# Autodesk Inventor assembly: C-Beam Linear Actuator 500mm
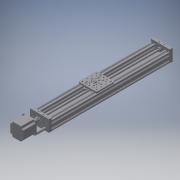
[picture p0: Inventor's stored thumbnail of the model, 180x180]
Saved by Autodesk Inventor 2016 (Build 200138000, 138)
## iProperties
Created: 2015-08
Part Number: C-Beam Linear Actuator 500mm
Description: STEP AP203
Document SubType Name: Assembly
Designer: John
Title: C-Beam Linear Actuator 500mm.step
Revision Number: ANY
Sending System: SolidWorks 2014
Preprocessor: SwSTEP 2.0
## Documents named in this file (19)
- D:\3D Printer Designs\John Ledden Designs\DLP Printer\STEP Parts Library 1.1\Assemblies\C-Beam Linear Actuator\C-Beam Linear Actuator 500mm.iam
- D:\3D Printer Designs\John Ledden Designs\DLP Printer\STEP Parts Library 1.1\Assemblies\C-Beam Linear Actuator\Low Profile Screw M5_M5 x 20.ipt
- D:\3D Printer Designs\John Ledden Designs\DLP Printer\STEP Parts Library 1.1\Assemblies\C-Beam Linear Actuator\Nylon Insert Lock Nut M5.ipt
- D:\3D Printer Designs\John Ledden Designs\DLP Printer\STEP Parts Library 1.1\Assemblies\C-Beam Linear Actuator\Low Profile Screw M5_M5 x 25.ipt
- D:\3D Printer Designs\John Ledden Designs\DLP Printer\STEP Parts Library 1.1\Assemblies\C-Beam Linear Actuator\Low Profile Screw M5_M5 x 55.ipt
- D:\3D Printer Designs\John Ledden Designs\DLP Printer\STEP Parts Library 1.1\Assemblies\C-Beam Linear Actuator\C-Beam End Mount.ipt
- D:\3D Printer Designs\John Ledden Designs\DLP Printer\STEP Parts Library 1.1\Assemblies\C-Beam Linear Actuator\C-Beam 40x80x500 Linear Rail.ipt
- D:\3D Printer Designs\John Ledden Designs\DLP Printer\STEP Parts Library 1.1\Assemblies\C-Beam Linear Actuator\Ball Bearing 8 x 16 x 5.ipt
- D:\3D Printer Designs\John Ledden Designs\DLP Printer\STEP Parts Library 1.1\Assemblies\C-Beam Linear Actuator\Shim Washer 8mm.ipt
- D:\3D Printer Designs\John Ledden Designs\DLP Printer\STEP Parts Library 1.1\Assemblies\C-Beam Linear Actuator\Lock Collar 8mm.ipt
- D:\3D Printer Designs\John Ledden Designs\DLP Printer\STEP Parts Library 1.1\Assemblies\C-Beam Linear Actuator\Aluminum Spacer 40mm.ipt
- D:\3D Printer Designs\John Ledden Designs\DLP Printer\STEP Parts Library 1.1\Assemblies\C-Beam Linear Actuator\Nema 23 Stepper Motor.ipt
- D:\3D Printer Designs\John Ledden Designs\DLP Printer\STEP Parts Library 1.1\Assemblies\C-Beam Linear Actuator\Flexible Coupling 0.25in x 8mm.ipt
- D:\3D Printer Designs\John Ledden Designs\DLP Printer\STEP Parts Library 1.1\Assemblies\C-Beam Linear Actuator\8mm leadscrew 540mm.ipt
- D:\3D Printer Designs\John Ledden Designs\DLP Printer\STEP Parts Library 1.1\Assemblies\C-Beam Linear Actuator\C-Beam Gantry Plate.ipt
- D:\3D Printer Designs\John Ledden Designs\DLP Printer\STEP Parts Library 1.1\Assemblies\C-Beam Linear Actuator\8mm Acme Nut Block.ipt
- D:\3D Printer Designs\John Ledden Designs\DLP Printer\STEP Parts Library 1.1\Assemblies\C-Beam Linear Actuator\Xtreme Mini V Wheel_Straight.iam
- D:\3D Printer Designs\John Ledden Designs\DLP Printer\STEP Parts Library 1.1\Assemblies\C-Beam Linear Actuator\Xtreme Mini V Wheel_Eccentric.iam
- D:\3D Printer Designs\John Ledden Designs\DLP Printer\STEP Parts Library 1.1\Assemblies\C-Beam Linear Actuator\Aluminum Spacer 3mm.ipt
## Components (40 placed, 40 different names)
1. Low Profile Screw M5_M5 x 20_1
2. Low Profile Screw M5_M5 x 20_2
3. Low Profile Screw M5_M5 x 20_3
4. Low Profile Screw M5_M5 x 20_4
5. Low Profile Screw M5_M5 x 20_5
6. Low Profile Screw M5_M5 x 20_6
7. Low Profile Screw M5_M5 x 20_7
8. Low Profile Screw M5_M5 x 20_8
9. Nylon Insert Lock Nut M5_9
10. Nylon Insert Lock Nut M5_10
11. Low Profile Screw M5_M5 x 20_11
12. Low Profile Screw M5_M5 x 20_12
13. Low Profile Screw M5_M5 x 25_13
14. Low Profile Screw M5_M5 x 25_14
15. Low Profile Screw M5_M5 x 25_15
16. Low Profile Screw M5_M5 x 25_16
17. Low Profile Screw M5_M5 x 55_17
18. Low Profile Screw M5_M5 x 55_18
19. C-Beam End Mount_19
20. C-Beam 40x80x500 Linear Rail_20
21. C-Beam End Mount_21
22. Ball Bearing 8 x 16 x 5_22
23. Ball Bearing 8 x 16 x 5_23
24. Shim Washer 8mm_24
25. Shim Washer 8mm_25
26. Lock Collar 8mm_26
27. Lock Collar 8mm_27
28. Aluminum Spacer 40mm_28
29. Aluminum Spacer 40mm_29
30. Nema 23 Stepper Motor_30
31. Flexible Coupling 0.25in x 8mm_31
32. 8mm leadscrew 540mm_32
33. C-Beam Gantry Plate_33
34. 8mm Acme Nut Block_34
35. Xtreme Mini V Wheel_Straight_35 [sub-assembly]
36. Xtreme Mini V Wheel_Straight_36 [sub-assembly]
37. Xtreme Mini V Wheel_Eccentric_37 [sub-assembly]
38. Xtreme Mini V Wheel_Eccentric_38 [sub-assembly]
39. Aluminum Spacer 3mm_39
40. Aluminum Spacer 3mm_40
